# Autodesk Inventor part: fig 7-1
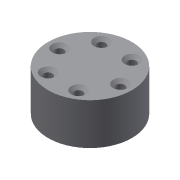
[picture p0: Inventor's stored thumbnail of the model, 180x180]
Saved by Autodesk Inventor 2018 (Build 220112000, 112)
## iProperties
Created: 2004-05
Part Number: fig 7-1
Document SubType Name: Modeling
Designer: CADCIM Technologies
Manufacturer: Standard
Standards Organization: Custom
Density: 1 g/cm^3
Material: Generic
Appearance: Default
Author: CADCIM Technologies
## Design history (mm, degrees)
sketch "Sketch1"
  geometry: C1 r 17.175 at (0, 0)
  constraints: 1 centre point
extrude "Extrusion1" new body sketch "Sketch1" distance "d0" = 17; taper "d1" = 0 deg
sketch "Sketch2"
  geometry: 1 further point
hole "Hole1" sketch "Sketch2" at (12.571, -0.074) diameter "d2" = 3.5; stored, may be unused: countersink angle "d6" = 90 deg, drill point angle "d8" = 118 deg; dims "d3" = 6, "d4" = 6, "d5" = 2, "d7" = 8
pattern_circular "Circular Pattern1" dims angle "d11" = 360 deg
body "Solid1"
